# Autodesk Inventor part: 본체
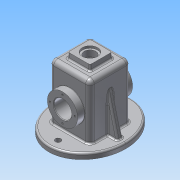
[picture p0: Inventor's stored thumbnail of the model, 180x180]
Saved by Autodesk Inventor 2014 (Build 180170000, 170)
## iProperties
Created: 2017-07
Part Number: 본체
Material: Aluminum 6061
Document SubType Name: Modeling
Designer: user
Density: 2.71 g/cm^3
Appearance: Aluminum - Flat
Mass: 895.116 g
Surface Area: 991.398 cm^2
Volume: 330.301 cm^3
Author: user
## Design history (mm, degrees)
sketch "Sketch1"
  geometry: 1 further point
sketch "Sketch2" dims "d1" = 65, "d2" = 75
  geometry: 2 further points; 1 other entity
  constraints: 1 coincident, 2 other
extrude "Extrusion1" new body sketch "Sketch2" distance "d3" = 10; taper "d4" = 0 deg
sketch "Sketch3"
  geometry: L1 (-37, 0)-(37, 0); L2 (37, 0)-(37, 110); L3 (37, 110)-(-37, 110); L4 (-37, 110)-(-37, 0); 2 further points
  constraints: 8 end point, 2 coincident, 2 parallel, 1 horizontal, 1 midpoint, 1 perpendicular
  dimensions: "d5" = 74 distance of L2.end L3.end; "d6" = 110 distance of L1.end L2.end
extrude "Extrusion2" join sketch "Sketch3" stored distance "d7" = 74; taper "d8" = 0 deg
sketch "Sketch4"
  geometry: L1 (-37, 110)-(37, 110) reference; L2 (-37, 10)-(37, 10) reference; L3 (-37, 10)-(-37, 110) reference; L4 (-37, 110)-(37, 110) reference; L5 (37, 110)-(37, 10) reference; L6 (-32, 105)-(-32, 0); L7 (32, 0)-(32, 105); L8 (32, 105)-(-32, 105); L9 (-75, 0)-(75, 0) reference; L10 (-32, 0)-(32, 0); 1 further point
  constraints: 8 end point, 2 point on line, 1 collinear
  dimensions: "d9" = 5 distance between parallel lines of L1 L8
extrude "Extrusion3" cut sketch "Sketch4" stored distance "d10" = 64; taper "d11" = 0 deg
sketch "Sketch5"
  geometry: L1 (17, 17)-(57, 17); L2 (57, 17)-(57, 57); L3 (57, 57)-(17, 57); L4 (17, 57)-(17, 17); L5 (17, 17)-(57, 57); L6 (57, 17)-(17, 57); 1 further point
  constraints: 12 end point, 2 midpoint, 2 parallel, 1 horizontal, 1 perpendicular
  dimensions: "d12" = 40 distance of L3.end L2.end; "d13" = 40 distance of L2.end L1.end
extrude "Extrusion4" join sketch "Sketch5" distance "d14" = 10; taper "d15" = 0 deg
sketch "Sketch6"
  geometry: 2 further points
  constraints: 1 coincident
hole "Hole1" sketch "Sketch6" at (37, 37) diameter "d16" = 21; stored, may be unused: countersink angle "d20" = 90 deg, drill point angle "d22" = 118 deg; dims "d17" = 6, "d18" = 28, "d19" = 4, "d21" = 8
feature "FaceDraft1" dims angle "d23" = 5 deg
sketch "Sketch7"
  geometry: L1 (10, -65)-(10, 65) reference; L2 (10, -65)-(10, 65) reference; L3 (0, 65)-(0, -65) reference; L4 (10, 55)-(102.248, 32); L5 (10, -55)-(102.248, -32); L6 (11.934, 54.518)-(64.26, 54.518); L7 (10, -55)-(75.922, -55); L8 (105, 32)-(0, 32) reference; L9 (0, -32)-(105, -32) reference; L10 (102.248, 32)-(10, 32); L11 (10, 37)-(10, -37) reference; L12 (102.248, -32)-(10, -32); 1 further point
  constraints: 12 end point, 9 point on line, 1 parallel, 1 perpendicular
  dimensions: "d24" = 10 distance of L4.start L1.end; "d25" = 10 distance of L1.start L5.start; "d26" = 14 deg angle of L6 L4; "d27" = 14 deg angle of L7 L5
extrude "Extrusion5" join sketch "Sketch7" stored distance "d28" = 10; taper "d29" = 0 deg
sketch "Sketch8"
  geometry: L1 (-75, 0)-(75, 0) reference; L2 (-37, 10)-(-37, 110) reference; L3 (37, 110)-(37, 10) reference; L4 (-32, 105)-(32, 105) reference; L5 (-32, 0)-(-32, 105) reference; L6 (32, 0)-(-32, 0) reference; L7 (32, 105)-(32, 0) reference; L8 (25, 75.5)-(25, 55); L9 (32, 82.5)-(25, 75.5); L10 (-32, 27.5)-(32, 27.5); L11 (-32, 82.5)-(-25, 75.5); L12 (50, 82.5)-(32, 82.5); L13 (32, 82.5)-(32, 27.5); L14 (-50, 55)-(-50, 82.5); L15 (-50, 82.5)-(-32, 82.5); L16 (-25, 75.5)-(-25, 55); L17 (50, 82.5)-(50, 55); L18 (-50, 55)-(-25, 55); L19 (25, 55)-(50, 55); L20 (-25, 55)-(25, 55); L21 (-50, 55)-(-32, 55); L22 (-32, 55)-(-32, 82.5); L23 (-32, 82.5)-(-50, 82.5); L24 (-50, 82.5)-(-50, 55); L25 (32, 55)-(50, 55); L26 (50, 55)-(50, 82.5); L27 (50, 82.5)-(32, 82.5); L28 (32, 82.5)-(32, 55); L29 (-32, 82.5)-(-25, 75.5); L30 (-25, 55)-(-32, 55); L31 (25, 55)-(25, 75.5); L32 (32, 82.5)-(32, 55); L33 (32, 105)-(32, 0) reference; L34 (32, 82.5)-(25, 75.5); L35 (25, 55)-(32, 55); 5 further points
  constraints: 54 end point, 7 collinear, 6 parallel, 4 perpendicular, 3 point on line, 2 coincident, 2 horizontal, 2 horizontal alignment, 1 midpoint
  dimensions: "d41" = 18 distance of L12.end L12.start; "d42" = 18 distance of L14.end L15.end; "d46" = 55 distance between parallel lines of L1 L20
revolve "Revolution1" sketch "Sketch8" stored, may be unused: angle "d47" = 90 deg
sketch "Sketch9"
  geometry: C1 r 27.5 at (0, 0) reference; C2 r 16 at (0, 0); 1 further point
  constraints: 1 centre point, 1 coincident
  dimensions: "d48" = 32 diameter of C2
extrude "Extrusion6" cut sketch "Sketch9" distance "d49" = 100; taper "d50" = 0 deg
sketch "Sketch10"
  geometry: C1 r 27.5 at (0, 0) reference; A1 r 22.5 centre (0, 0) between (0, 22.5) and (-22.5, 0); 3 further points
  constraints: 4 point on circle, 1 centre point, 1 coincident
  dimensions: "d51" = 45 diameter of A1
hole "Hole2" sketch "Sketch10" at (0, 22.5), (-22.5, 0), (0, -22.5), (22.5, 0) diameter "d52" = 3.242; stored, may be unused: countersink angle "d56" = 90 deg, drill point angle "d58" = 118 deg; dims "d53" = 8, "d54" = 28, "d55" = 4, "d57" = 10
mirror "Mirror1"
sketch "Sketch11"
  geometry: L1 (58, -19.058)-(-58, -19.058); L2 (-58, -19.058)-(-58, 19.058); L3 (-58, 19.058)-(58, 19.058); L4 (58, 19.058)-(58, -19.058); L5 (58, -19.058)-(-58, 19.058); L6 (-58, -19.058)-(58, 19.058); 3 further points; 1 other entity
  constraints: 12 end point, 4 midpoint, 2 parallel, 1 horizontal, 1 perpendicular, 1 other
  dimensions: "d59" = 116 distance of L2.end L3.end
hole "Hole3" sketch "Sketch11" at (-58, 0), (58, 0) diameter "d60" = 10; stored, may be unused: countersink angle "d64" = 90 deg, drill point angle "d66" = 118 deg; dims "d61" = 8, "d62" = 28, "d63" = 4, "d65" = 10
chamfer "Chamfer1" distance "d67" = 1; stored, may be unused: second distance "d68" = 2, angle "d69" = 45 deg
fillet "Fillet1" dims "d70" = 8
fillet "Fillet2" dims "d71" = 3
fillet "Fillet3" dims "d72" = 3
fillet "Fillet4" dims "d73" = 3
fillet "Fillet5" dims "d74" = 3
fillet "Fillet6" dims "d75" = 0.5
fillet "Fillet7" dims "d76" = 3
fillet "Fillet8" dims "d77" = 3
fillet "Fillet9" dims "d78" = 3
fillet "Fillet10" dims "d79" = 3
fillet "Fillet11" dims "d80" = 3
workplane "Work Plane1"
sketch "Sketch14"
  geometry: L1 (120, 17.011)-(120, -17.011) reference; L2 (13, -37)-(102, -37) reference; 2 further points
  constraints: 1 other
  dimensions: "d90" = 30 distance from line of L1 point (90, 0); "d91" = 37 distance from line of L2 point (90, 0)
emboss "Emboss3" sketch "Sketch14" dims "d1" = 65, "d2" = 75, "d9" = 5, "d92" = 0.5, "d93" = 0
fillet "Fillet12" dims "d94" = 0.5
fillet "Fillet13" dims "d95" = 3
body "Solid1"
node "Projected Loop1"
node "Projected Loop2"
node "Projected Loop3"
other parameters: "d31" = 7
